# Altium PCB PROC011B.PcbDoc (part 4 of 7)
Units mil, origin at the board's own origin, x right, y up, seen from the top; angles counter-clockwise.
Board outline 3304 x 2569 mil, 6 copper layers (TOP, L2-GND1, L3-GND/SIG, L4-GND/SIG, L5-GND2, BOTTOM), stack 55.77 mil thick; 376 components, 289 nets, 1284 pads, 1755 vias.
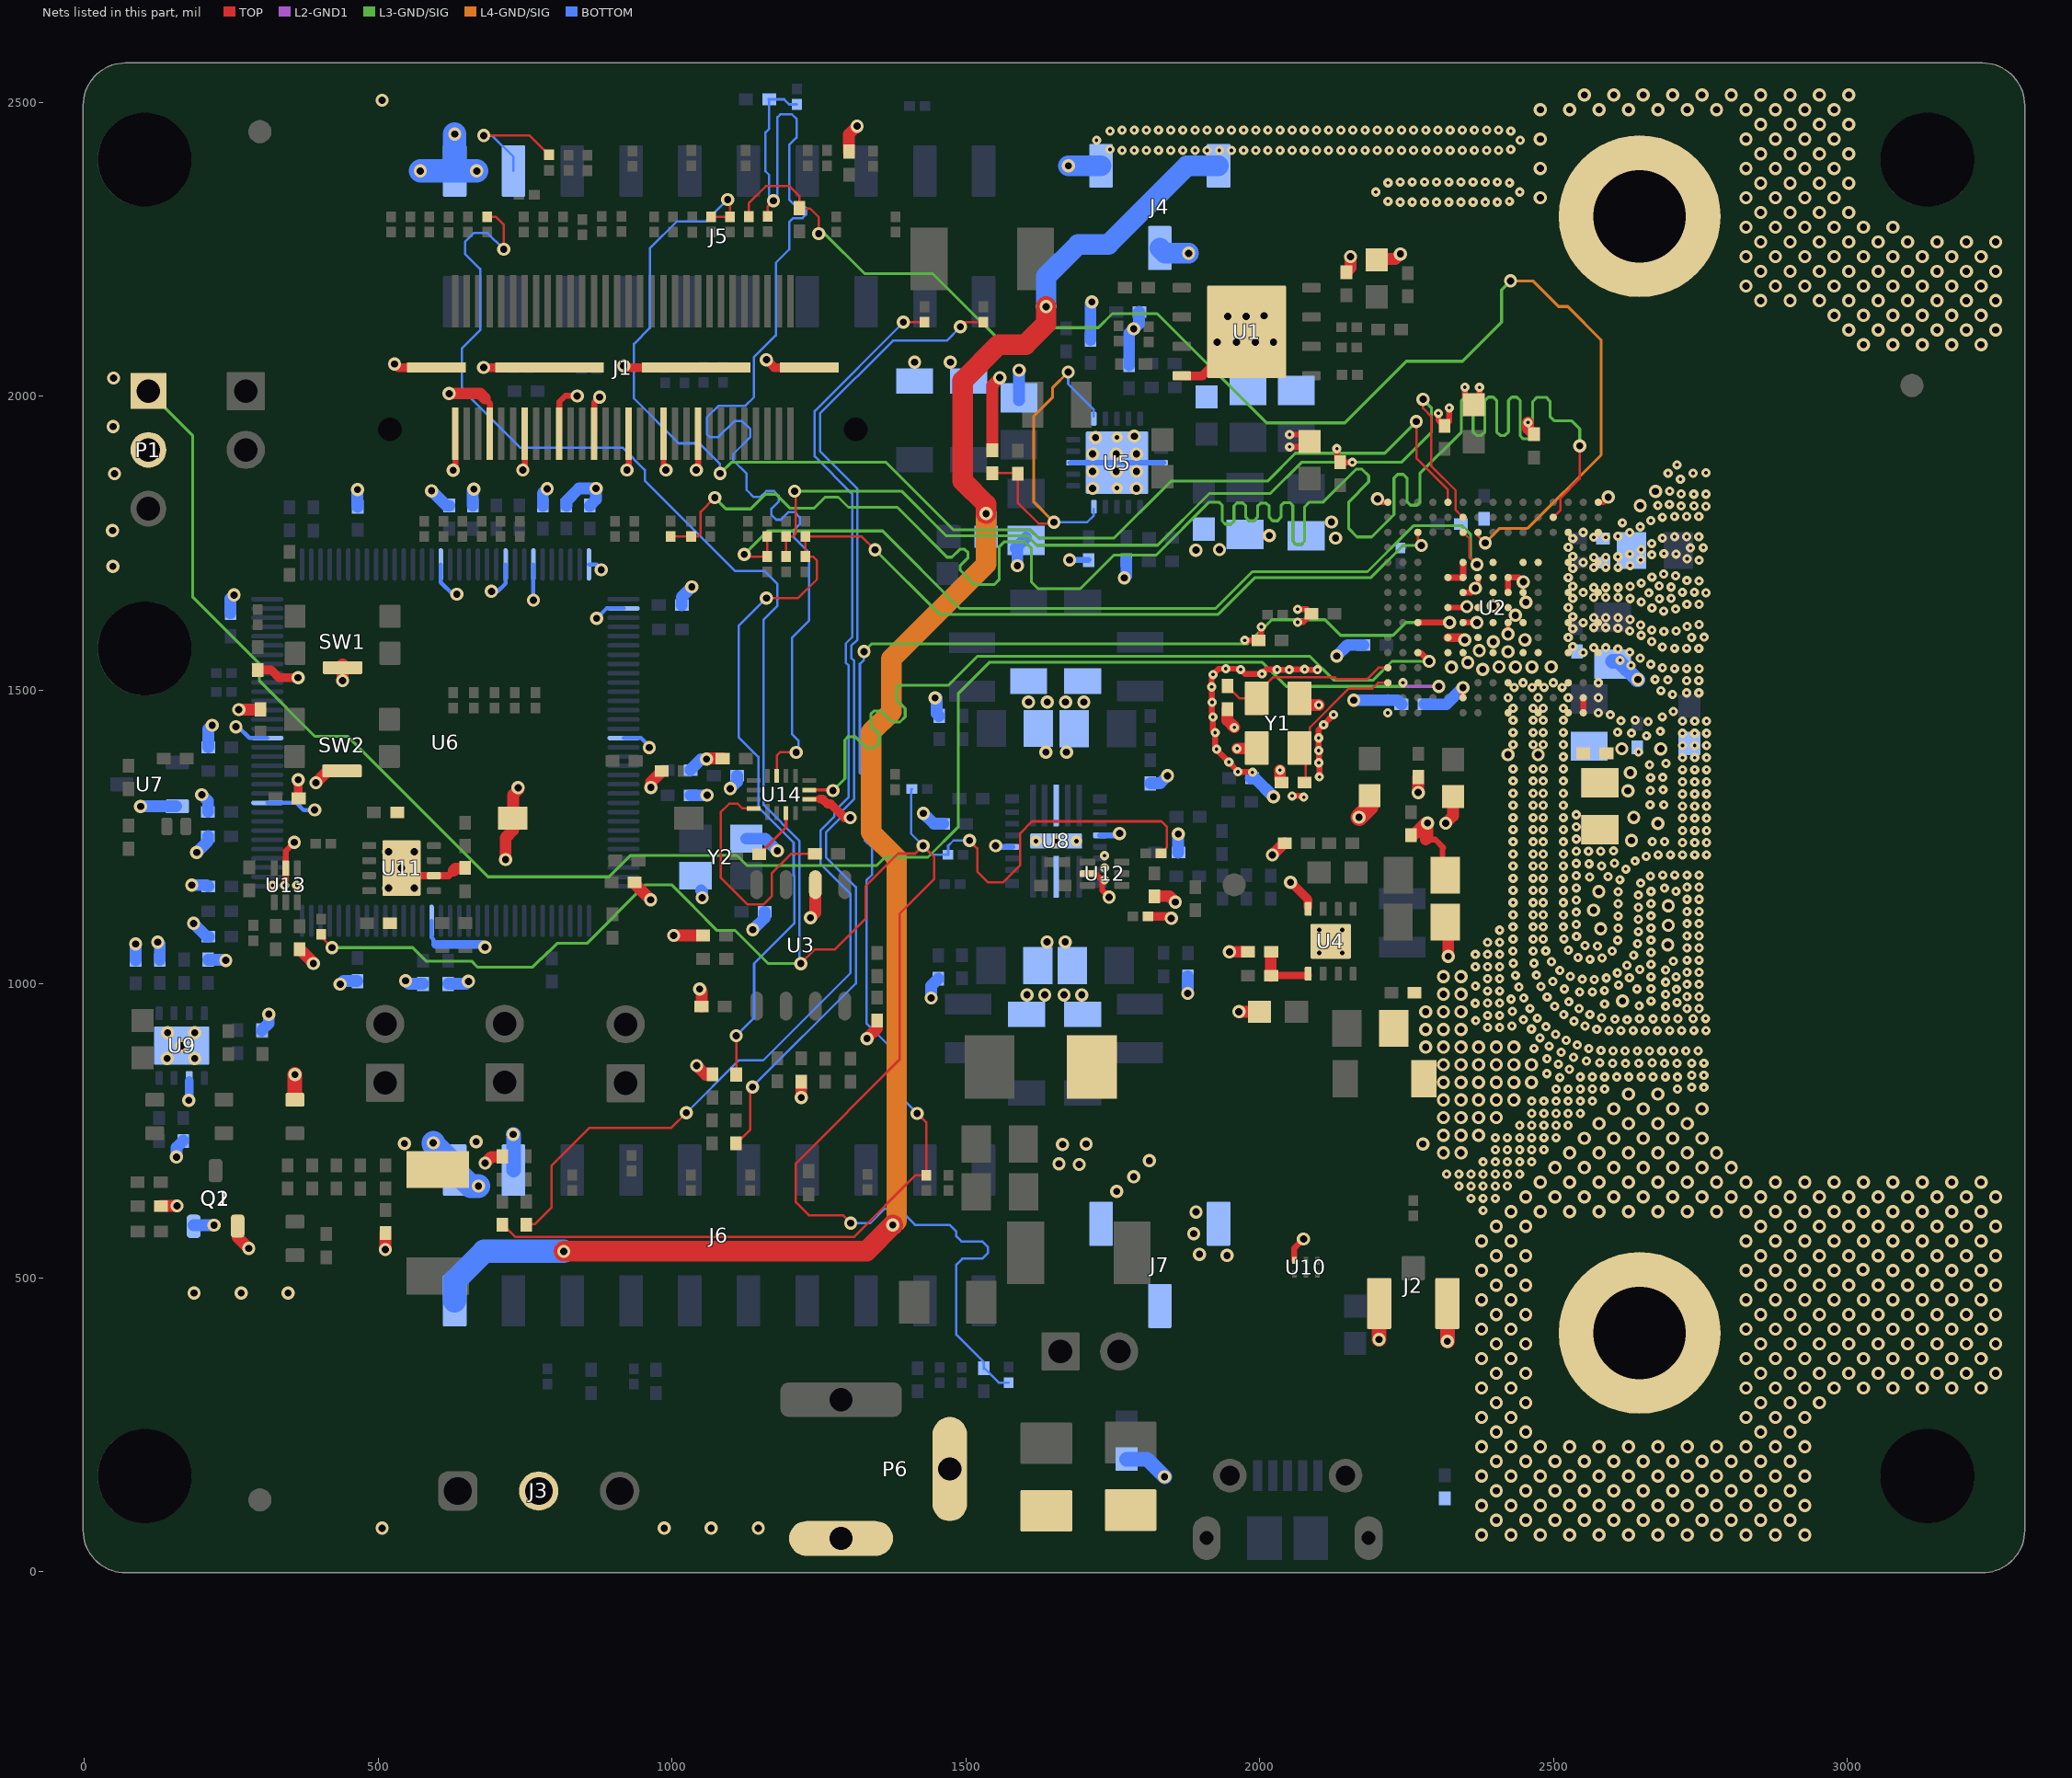
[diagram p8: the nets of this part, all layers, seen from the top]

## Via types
v1: diameter 22.4, hole 12.2, TOP to BOTTOM, tented both sides, 1046 vias
v2: diameter 13.77/15.74 (per signal layer), hole 5.9, TOP to L2-GND1, tented both sides, 699 vias
v3: diameter 19.68, hole 7.87, TOP to BOTTOM, tented both sides, 9 vias
v4: diameter 15.74, hole 5.9, TOP to L2-GND1, tented both sides, 1 vias

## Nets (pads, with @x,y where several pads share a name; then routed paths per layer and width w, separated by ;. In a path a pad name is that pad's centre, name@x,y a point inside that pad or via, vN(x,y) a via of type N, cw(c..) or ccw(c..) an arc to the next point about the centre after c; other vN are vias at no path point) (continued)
AR_SDA: R23.1 R144.2 R162.1 R168.2 R170.1 R199.2 R211.1 | length 5223.1
  TOP w4: R199.2@403.05,1084.31 403.05,1080.1 v1(421.55,1061.6) ; R23.1@685.36,2305.21 700.04,2305.21 713.75,2291.5 v1(713.75,2250) ; v1(1219.15,1034.5) 1243.45,1058.8 1277.45,1058.8 1329.5,1110.85 1329.5,1166.5 1384.75,1221.75 1413.95,1221.75 v1(1427.37,1235.17) 1446.25,1216.29 1446.25,1178.6 1387.15,1119.5 1387.15,870.9 1210.75,694.5 1210.75,628.61 1232.86,606.5 1290.75,606.5 v1(1304.25,593) ; v1(1506.45,1244.07) 1506.45,1243.8 1519.65,1230.6 1519.65,1191.2 1538.35,1172.5 1563.04,1172.5 1592.55,1202.01 1592.55,1256.3 1612.75,1276.5 1833.14,1276.5 1842.05,1267.59 1842.05,1232.11 R168.2@1832.34,1222.4
  L3-GND/SIG w5: v1(421.55,1061.6) 558.75,1061.6 581.55,1038.8 659.05,1038.8 669.55,1028.3 762.45,1028.3 776.95,1042.8 778.15,1042.8 804.35,1069 855.35,1069 955.01,1168.66 999.45,1168.66 1037.45,1130.66 1037.45,1130.19 1076.79,1090.85 1107.71,1090.85 1164.06,1034.5 v1(1219.15,1034.5)
  BOTTOM w4: v1(713.75,2250) 686.25,2277.5 662.75,2277.5 647.75,2262.5 647.75,2242.5 673.75,2216.5 673.75,2112.5 642.75,2081.5 642.75,2011.5 741.75,1912.5 915.75,1912.5 953.75,1874.5 953.75,1863.8 953.65,1863.7 953.65,1856.3 1107.45,1702.5 1157.75,1702.5 1179.65,1680.6 1179.65,1643.6 1155.92,1619.87 1155.92,1304.36 1217.15,1243.13 1217.15,1036.5 v1(1219.15,1034.5) ; v1(1304.25,593) 1337.45,593 1361.95,617.5 1386.15,617.5 1413.65,590 1472.2,590 1483.75,578.45 1483.75,570.43 1492.38,561.8 1528.27,561.8 1537.97,552.1 1537.97,542.78 1527.72,532.53 1494.11,532.53 1483.75,522.17 1483.75,403 1530.77,355.98 R170.1@1530.77,346.04 1530.77,345.25 1532.49,345.25 1555.95,321.79 R162.1@1573,321.79 ; R211.1@1408.17,1331.73 1407.05,1330.61 1407.05,1255.49 v1(1427.37,1235.17) 1442.94,1219.6 R144.2@1469.76,1219.6 1470.06,1219.6 1470.06,1235.11 1479.02,1244.07 v1(1506.45,1244.07)
AR_SPICLK1: U2.E13 U14.7 | length 1373.8
  TOP w5: U14.7@1233.51,1330.08 1272.86,1330.08 v1(1274.01,1328.93)
  TOP w10: U2.E13@2269.35,1563.63 2273.63,1563.63 v1(2288.46,1548.8)
  L3-GND/SIG w5: v1(1274.01,1328.93) 1294.43,1349.35 1294.43,1415.08 1299.93,1420.59 1311.84,1420.59 1330.71,1401.72 1344.05,1401.72 1353.12,1410.79 1353.12,1423.66 1353.6,1424.14 1338.32,1439.42 1338.32,1458.98 1343.72,1464.37 1355.7,1464.37 1374.57,1445.5 1387.91,1445.5 1396.98,1454.57 1396.98,1468.4 1382.18,1483.2 1382.18,1502.76 1387.55,1508.13 1387.55,1508.2 1470.56,1508.2 1519.86,1557.5 2085.36,1557.5 2125.86,1517 2193.35,1517 2225.15,1548.8 v1(2288.46,1548.8)
AR_SYNC_IN: R62.2 R165.1 U2.P4 | length 3219.4
  TOP w4: R165.1@997.75,1761.51 1032.32,1761.51 R62.2@1032.6,1761.23 1044.08,1761.23 1048.75,1765.9 1048.75,1803.5 v1(1072.75,1827.5) ; U2.P4@2499.66,1793.94 2512.25,1806.53 2512.25,1826.82 2544.75,1859.32 v1(2544.75,1915.5)
  L3-GND/SIG w5: v1(1072.75,1827.5) 1091.85,1808.4 1133.95,1808.4 1158.95,1833.4 1176.85,1833.4 1201.05,1809.2 1241.45,1809.2 1260.45,1828.2 1282.95,1828.2 1300.15,1811 1383.25,1811 1468.04,1726.21 1476.32,1726.21 1489.69,1739.58 1497.97,1739.58 1503.84,1733.71 1503.84,1725.43 1490.47,1712.06 1490.47,1703.78 1514.75,1679.5 1548.75,1679.5 1556.75,1687.5 1556.75,1743.5 1565.75,1752.5 1599.75,1752.5 1611.75,1740.5 1611.75,1683.5 1622.75,1672.5 1694.75,1672.5 1751.75,1729.5 1823.65,1729.5 1913.55,1819.4 1931.45,1819.4 1936.45,1814.4 1936.45,1787.45 1941.45,1782.45 1951.41,1782.45 1956.45,1787.49 1956.45,1813.3 1961.45,1818.3 1971.45,1818.3 1976.45,1813.3 1976.45,1793.91 1982.31,1788.05 1990.59,1788.05 1996.45,1793.91 1996.45,1812.9 2001.45,1817.9 2011.45,1817.9 2016.45,1812.9 2016.45,1793.91 2022.31,1788.05 2030.59,1788.05 2036.45,1793.91 2036.45,1813.9 2041.45,1818.9 2051.45,1818.9 2056.45,1813.9 2056.45,1753.05 2061.45,1748.05 2071.45,1748.05 2076.45,1753.05 2076.45,1811.4 2084.85,1819.8 2108.05,1819.8 2164.05,1875.8 2174.35,1875.8 2185.76,1864.39 2185.76,1854.21 2151.75,1820.2 2151.75,1774.5 2165.75,1760.5 2190.75,1760.5 2228.75,1798.5 2228.75,1860.9 2234.75,1866.9 2244.75,1866.9 2250.75,1860.9 2250.75,1820.49 2256.74,1814.5 2267.75,1814.5 2272.75,1819.5 2272.75,1868.5 2343.41,1939.16 2343.41,1992.64 2349.27,1998.5 2357.55,1998.5 2363.41,1992.64 2363.41,1939.16 2369.27,1933.3 2377.55,1933.3 2383.41,1939.16 2383.41,1992.64 2389.27,1998.5 2397.55,1998.5 2403.41,1992.64 2403.41,1939.16 2409.27,1933.3 2417.55,1933.3 2423.41,1939.16 2423.41,1992.64 2429.27,1998.5 2437.55,1998.5 2443.41,1992.64 2443.41,1932.54 2448.45,1927.5 2459.65,1927.5 2464.65,1932.5 2464.65,1990.7 2472.05,1998.1 2487.65,1998.1 2494.25,1991.5 2494.25,1965.3 2501.25,1958.3 2530.55,1958.3 2544.75,1944.1 v1(2544.75,1915.5)
AR_SYNC_OUT_SOP1: R108.2 R113.1 U2.G13 | length 2815.8
  TOP w4: R113.1@711.67,591.15 712.06,590.76 733.52,569.3 1309.54,569.3 1414.81,674.57 R108.2@1433.1,674.57 1433.1,763.85 v1(1417.3,779.65)
  TOP w10: U2.G13@2269.35,1614.81 2305.01,1614.81 2305.1,1614.9 v1(2323.3,1614.9)
  L3-GND/SIG w5: v1(1326.75,1565.5) 1340.05,1578.8 1980.05,1578.8 2020.85,1619.6 2111.35,1619.6 2137.85,1593.1 2226.95,1593.1 2248.75,1614.9 v1(2323.3,1614.9)
  BOTTOM w4: v1(1326.75,1565.5) 1326.75,1551.2 1319.75,1544.2 1319.75,1359.13 1327.71,1351.17 1327.71,1244.52 1340.53,1231.7 1340.53,1185.67 1330.95,1176.09 1330.95,933.2 1367.55,896.6 1367.55,829.4 v1(1417.3,779.65)
AR_TCK: R66.2 R70.1 U2.P10 | length 1617.8
  TOP w4: R70.1@1194.08,1727.21 1194.5,1727.63 R66.2@1194.5,1761.23 1205.48,1761.23 1210.75,1766.5 1210.75,1836.5 v1(1208.75,1838.5) ; v1(2278.15,1994.7) 2278.15,1979.6 2292.35,1965.4 2292.35,1880.9 2333.55,1839.7 2333.55,1806.54 2336.44,1803.65 2336.44,1803.55 2346.05,1793.94 U2.P10@2346.12,1793.94
  L3-GND/SIG w5: v1(1208.75,1838.5) 1390.35,1838.5 1466.35,1762.5 1604.75,1762.5 1620.75,1746.5 1826.45,1746.5 1914.45,1834.5 2018.15,1834.5 2071.15,1887.5 2241.45,1887.5 2292.35,1938.4 2292.35,1980.5 v1(2278.15,1994.7)
AR_TDI: R29.1 R30.1 U2.R11 | length 2192.5
  TOP w4: R29.1@1066.58,2305.21 R30.1@1098.5,2305.21 1098.5,2330.75 v1(1094.75,2334.5) ; v1(2266.75,1956.9) 2266.75,1894.5 2320.53,1840.72 U2.R11@2320.53,1819.53
  L3-GND/SIG w5: v1(1081.75,1868.5) 1100.75,1887.5 1364.35,1887.5 1479.35,1772.5 1609.75,1772.5 1623.75,1758.5 1752.05,1758.5 1849.05,1855.5 2013.35,1855.5 2060.85,1903 2212.85,1903 v1(2266.75,1956.9)
  BOTTOM w4: v1(1081.75,1868.5) 1081.75,1884.5 1046.48,1919.77 1011.72,1919.77 935.45,1996.04 935.45,2089.06 962.51,2116.12 962.51,2251.26 1008.75,2297.5 1057.75,2297.5 v1(1094.75,2334.5)
AR_TDO_SOP0: R67.2 R71.1 R89.1 U2.N13 | length 2275.2
  TOP w4: v1(1109.25,911.8) 1109.33,911.72 R89.1@1109.33,845.74 R89.1@1109.33,844.95 ; v1(1160.75,1656.5) 1214.75,1656.5 1246.75,1688.5 1246.75,1720.5 1240.04,1727.21 R71.1@1227.08,1727.21 1227,1727.29 R67.2@1227,1761.23 1323.02,1761.23 v1(1345.65,1738.6) ; U2.N13@2269.35,1768.35 2269.35,1752 v1(2275.25,1746.1)
  L3-GND/SIG w5: v1(1345.65,1738.6) 1455.45,1628.8 1929.45,1628.8 1992.15,1691.5 2189.55,1691.5 2244.15,1746.1 v1(2275.25,1746.1)
  BOTTOM w4: v1(1109.25,911.8) 1139.75,942.3 1139.75,1034.5 1208.15,1102.9 1208.15,1183.39 1207.05,1184.49 1207.05,1240.5 1146.92,1300.63 1146.92,1386.08 1113.84,1419.16 1113.84,1609.59 v1(1160.75,1656.5)
AR_TMS: R65.2 R69.1 U2.N10 | length 1566.1
  TOP w4: v1(1123.11,1730.85) 1126.75,1727.21 R69.1@1162,1727.21 R65.2@1162,1761.23 ; U2.N10@2346.12,1768.35 2357.07,1757.4 2357.07,1726.57 v1(2369.94,1713.7)
  L3-GND/SIG w5: v1(1123.11,1730.85) 1162.86,1770.6 1358.45,1770.6 1490.25,1638.8 1925.25,1638.8 1987.95,1701.5 2183.75,1701.5 2261.75,1779.5 2344.75,1779.5 2358.75,1765.5 2358.75,1724.89 v1(2369.94,1713.7)
AR_VBGAP: C56.2 U2.B10 | length 95.2
  TOP w10: U2.B10@2346.12,1486.86 v1(2346.12,1504.3)
  BOTTOM w20: C56.2@2280.2,1475.8 C56.2@2280.59,1475.8 2317.62,1475.8 v1(2346.12,1504.3)
AR_VOUT_PA: C10.2 C65.2 C83.2 R137.2 U2.A2 U2.B2 | length 44.9
  TOP w10: U2.A2@2550.84,1461.27 U2.B2@2550.84,1486.86 ; C83.2@2579.15,1342.15 C83.2@2592.8,1328.5
  other v1: 2626.75,1328.5 2630.75,1359.5
AR_VSENSE: P1.1 U2.C14 | length 3095.5
  L2-GND1 w5: v2(2243.76,1512.45) 2249.91,1506.3 v1(2304.85,1506.3)
  L3-GND/SIG w5: P1.1@109.02,2008.65 184.25,1933.42 184.25,1658.5 297.95,1544.8 297.95,1515.3 391.75,1421.5 447.65,1421.5 686.85,1182.3 893.05,1182.3 929.45,1218.7 1079.78,1218.7 1079.92,1218.56 1110.25,1218.56 1127.41,1201.4 1348.65,1201.4 1362.72,1215.47 1435.53,1215.47 1487.45,1267.39 1487.45,1494.47 1540.13,1547.15 2004.69,1547.15 2045.54,1506.3 v1(2304.85,1506.3)
AR_WARMRST: R15.1 R18.1 U2.N9 | length 2374.3
  TOP w4: R18.1@1130.96,2305.56 1130.96,2328.72 1159.74,2357.5 1199.74,2357.5 1216.75,2340.49 R15.1@1216.75,2320.04 1216.75,2319.25 1234.99,2319.25 1249.75,2304.49 v1(1249.75,2276.5) ; U2.N9@2371.71,1768.35 2371.71,1762.58 v1(2383.94,1750.35)
  L3-GND/SIG w5: v1(1249.75,2276.5) 1259.75,2276.5 1327.75,2208.5 1443.74,2208.5 1511.74,2140.5 1561.75,2090.5 1624.55,2090.5 1650.75,2116.7 1725.55,2116.7 1749.35,2140.5 1825.65,2140.5 2011.65,1954.5 2144.85,1954.5 2249.85,2059.5 2345.25,2059.5 2411.75,2126 2411.75,2181 v1(2426.95,2196.2)
  L4-GND/SIG w5: v1(2383.94,1750.35) 2408.69,1775.1 2456.15,1775.1 2581.15,1900.1 2581.15,2095.7 2524.35,2152.5 2508.95,2152.5 2465.25,2196.2 v1(2426.95,2196.2)
AR_XTALM: C9.2 U2.D15 Y1.1 | length 310.5
  TOP w4: C9.2@1945.11,1506.53 1965.68,1485.96 Y1.1@1995.05,1485.96 1995.05,1494.1 2022.55,1521.6 2128.25,1521.6 2131.35,1518.5 2182.76,1518.5 2202.3,1538.04 U2.D15@2218.17,1538.04
AR_XTALP: C15.2 U2.C15 Y1.3 | length 269.3
  TOP w4: C15.2@2078.45,1342.9 2078.28,1343.07 2078.28,1390.93 Y1.3@2067.89,1401.32 2085.45,1418.88 2085.45,1436.2 2151.75,1502.5 2191.75,1502.5 2201.7,1512.45 U2.C15@2218.17,1512.45
CAN_RX: R12.1 U14.3 | length 88.9
  TOP w5: R12.1@1148.6,1220.7 1148.6,1220.88 1194.14,1266.43 U14.3@1194.14,1290.71
CAN_TX: R11.1 U14.16 | length 414.6
  TOP w4: U14.16@1139.03,1298.59 1119.85,1298.59 1111.77,1306.66 1097.53,1306.66 1082.75,1291.88 1082.75,1181.16 1128.82,1135.09 1155.63,1135.09 1170.22,1149.68 1170.22,1188.61 1203.03,1221.42 R11.1@1243.26,1221.42
CS1: R1.2 R14.1 R17.1 U14.11 | length 2014.1
  TOP w4: R17.1@1163,2306.21 1163,2322.75 v1(1172.75,2332.5) ; U14.11@1178.4,1353.71 1178.4,1388.61 1183.82,1394.03 v1(1211.3,1394.03)
  BOTTOM w4: R14.1@1164.55,2505.1 1164.94,2504.71 R14.1@1165.33,2504.32 ; v1(1211.3,1394.03) 1215.55,1398.28 1215.55,1413.8 1204.58,1424.77 1204.58,1589.33 1233.65,1618.4 1233.65,1733.6 1207.37,1759.88 1207.37,1771.75 1217.45,1781.83 1217.45,1793.84 1208.44,1802.85 1198.4,1802.85 1185.43,1789.88 1177.37,1789.88 1169.46,1797.79 1169.46,1808.62 1181.52,1820.68 1181.52,1830.71 1173.46,1838.77 1160.66,1838.77 1150.25,1828.36 1138.89,1828.36 1126.93,1840.32 1126.93,1867.97 1104.17,1890.73 1104.17,1901.36 1133.26,1930.45 1133.26,1943.7 1118.91,1958.05 1106.58,1958.05 1079.08,1930.56 1064.35,1930.56 1059.53,1935.37 1059.53,1964.01 1079.32,1983.8 1125.15,1983.8 1139.72,1998.38 1139.72,2066.57 1176.75,2103.6 1176.75,2226.9 1199.45,2249.6 1199.45,2295.83 1206.59,2302.97 1222.11,2302.97 1228.57,2309.43 1228.57,2319.78 1221.17,2327.18 1206.59,2327.18 1199.45,2334.32 1199.45,2427.51 1212.05,2440.11 1212.05,2471.94 1204.37,2479.62 1184.3,2479.62 1179.41,2474.73 1179.41,2339.16 v1(1172.75,2332.5) 1165.33,2339.92 1165.33,2376.39 1159.09,2382.63 1159.09,2448.81 1165.33,2455.05 R14.1@1165.33,2504.32 ; R14.1@1165.33,2504.32 R14.1@1165.33,2505.1 1190.75,2505.1 1199.34,2496.51 ; 1199.34,2496.51 R1.2@1212.55,2496.51 1199.34,2496.51
D_LOGGER: J5.4 R60.1 | length 214.1
  TOP w4: v1(679.75,2443.5) 757.74,2443.5 R60.1@790.75,2410.49
  BOTTOM w4: v1(679.75,2443.5) 693.75,2443.5 730.25,2407 J5.4@730.25,2383.22
GND: C1.1 C2.1 C3.1 C4.1 C5.1 C6.1 C7.1 C8.1 C9.1 C10.1 C11.1 C12.1 C13.1 C14.1 C15.1 C16.1 C17.1 C19.1 C20.1 C21.1 C22.1 C23.1 C24.1 C25.1 C26.2 C27.2 C29.1 C30.1 C31.1 C32.1 C33.1 C34.1 C35.1 C36.1 C37.1 C38.1 C39.1 C40.1 C41.1 C42.1 C43.1 C44.1 C45.1 C47.1 C48.1 C49.1 C50.1 C51.1 C52.1 C53.1 C54.1 C55.1 C56.1 C57.1 C58.1 C59.1 C60.1 C61.1 C62.1 C63.1 C64.1 C65.1 C66.1 C67.1 C68.1 C69.1 C70.1 C71.1 C72.1 C73.1 C74.1 C75.1 C76.1 C77.1 C79.1 C80.1 C81.1 C82.1 C83.1 C84.1 C85.1 C86.1 C87.1 C89.1 C90.1 C91.1 C92.1 C93.1 C94.1 C95.1 C96.1 C97.1 D3.2 DS2.2 J1.18 J1.24 J1.30 J1.36 J1.42 J1.48 J1.54 J1.60 J1.MP1 J1.MP2 J1.MP3 J1.MP4 J2.2 J2.3 J3.2 J4.1 J4.2 J5.2 J6.4 J7.1 J7.2 P1.2 P6.2 P6.3 pad.1 pad.2 Q1.2 Q2.2 R13.1 R47.2 R73.1 R79.1 R81.1 R83.2 R86.2 R88.1 R96.1 R110.1 R114.1 R119.1 R121.1 R123.2 R125.1 R126.2 R132.1 R138.1 R139.1 R153.1 R157.1 R158.1 R167.1 R174.1 R175.1 R193.1 R208.2 S2.1 SW1.5 SW2.5 U1.4 U1.9 U2.A1 U2.A3 U2.A5 U2.A7 U2.A15 U2.B1 U2.B3 U2.B5 U2.B7 U2.C1 U2.C3 U2.C4 U2.C5 U2.C6 U2.C7 U2.E1 U2.E2 U2.E3 U2.E5 U2.E6 U2.E8 U2.E10 U2.E11 U2.F3 U2.F9 U2.F11 U2.G1 U2.G2 U2.G3 U2.G6 U2.G7 U2.G8 U2.G10 U2.H3 U2.H7 U2.H9 U2.H11 U2.J1 U2.J2 U2.J3 U2.J6 U2.J7 U2.J8 U2.J10 U2.K3 U2.K7 U2.K8 U2.K9 U2.K10 U2.K11 U2.L1 U2.L2 U2.L3 U2.L5 U2.L6 U2.L8 U2.L10 U2.M3 U2.N1 U2.N2 U2.N3 U2.R1 U2.R15 U3.2 U4.4 U4.9 U5.3 U5.13 U5.21@1757.37,1886.82 U6.10 U6.17 U6.48 U6.55 U6.58 U6.64 U6.66 U6.80 U6.114 U7.2 U8.4 U8.11 U8.17 U8.24 U8.27 U9.6 U9.9 U10.3 U11.6 U11.9 U12.2 U13.2 U14.6 Y1.2 Y1.4 Y2.2 Y2.4 | length 8140.2
  TOP w7: U14.6@1233.51,1314.34 1252.42,1314.34 ; U2.J7@2421.64,1665.99 U2.J7@2422.89,1665.99 U2.J7@2423.36,1665.99 ; U2.G7@2422.89,1614.81 U2.G7@2422.89,1614.81 v1@2422.89,1595.21
  TOP w9: v1(2367.2,1673.3) 2371.71,1677.81 U2.K9@2371.71,1691.58
  TOP w10: v2@342.75,1175.5 342.75,1226.3 v1(357.35,1240.9) ; v1(627.73,1874.03) 631.37,1877.67 J1.60@631.37,1935.77 ; 681.75,1996.5 690.42,1987.83 J1.54@690.42,1935.77 ; v1(746.28,1874.47) 749.48,1877.67 J1.48@749.48,1935.77 ; J1.42@808.53,1935.77 808.53,1990.5 818.53,2000.5 v1(838.75,2000.5) ; J1.36@867.59,1935.77 867.59,1989.34 v1(876.75,1998.5) ; v1(923.36,1874.39) 926.64,1877.67 J1.30@926.64,1935.77 ; J1.24@985.7,1935.77 985.7,1878.55 v1(989.75,1874.5) ; v1(1041.42,1874.34) 1044.75,1877.67 J1.18@1044.75,1935.77 ; U12.2@1707.12,1187.4 1720.95,1187.4 1732.15,1176.2 1732.15,1159.4 v1(1743.95,1147.6) ; v2(1974.75,1584.5) C84.1@1998.07,1584.5 1998.45,1584.5 2002.75,1588.8 v2(2002.75,1607.5) ; v2(1987.75,1360) 1987.75,1360.9 v2(1962.85,1360.9) 1962.85,1362.4 v2(1947.75,1377.5) 1926.75,1398.5 v2(1926.75,1399.5) 1924.35,1401.9 v2(1924.35,1427.5) 1920.45,1431.4 v2(1920.45,1454) 1919.05,1455.4 v2(1919.05,1479.1) 1919.05,1504.8 v2(1918.45,1505.4) 1918.45,1524.2 v2(1920.75,1526.5) 1930.65,1536.4 v2(1942.45,1536.4) 1966.35,1536.4 v2(1967.75,1535) 1975.35,1527.4 v2(2004.05,1527.4) 2011.55,1534.9 v2(2029.75,1534.9) 2030.15,1534.5 v2(2050.35,1534.5) 2051.18,1535.33 v2(2076.77,1535.33) 2077.7,1534.4 2098.45,1534.4 v2(2098.55,1534.5) ; v2(2051.05,1913.8) 2075.75,1913.8 C89.1@2084.85,1922.9 2073.15,1934.6 v2(2051.05,1934.6) ; v2(2055.37,1319.8) 2073.05,1319.8 v2(2075.15,1317.7) ; U10.3@2059.07,529.81 2059.06,550.31 v1(2074.75,566) ; v2(2064.75,1615.5) 2074.07,1615.5 2088.42,1629.85 2080.77,1637.5 v2(2064.75,1637.5) ; v2(2101.85,1352.2) 2101.85,1375.3 v2(2100.85,1376.3) 2100.85,1396.5 v2(2100.45,1396.9) v2(2100.45,1418.6) 2100.45,1432.5 v2(2108.95,1441) v2(2125.9,1457.95) ; v2(2131.55,1910.8) 2131.55,1893.1 2137.25,1887.4 v2(2158.05,1887.4) ; v1(2200.75,1825.3) 2206.52,1819.53 U2.R15@2218.17,1819.53 ; C90.1@2261.63,1253.2 2275.05,1253.2 2282.75,1245.5 2298.85,1245.5 2312.55,1231.8 2311.25,1230.5 C17.1@2311.25,1185.1 ; v2(2304.15,1970.9) 2304.15,1959.4 2314.15,1949.4 2314.7,1949.4 2322.65,1957.35 v2(2322.65,1980.3) ; U2.H11@2320.53,1640.4 2351.3,1640.4 v1(2352.8,1641.9) ; U2.G10@2346.12,1614.81 v1@2369.69,1614.81 ; U2.J10@2346.12,1665.99 2359.89,1665.99 v1(2367.2,1673.3) ; v2(2349.35,2015.2) 2349.35,2000.05 2364,1985.4 C87.1@2364.55,1985.4 2374.25,1995.1 v2(2374.25,2015) ; U2.J7@2422.89,1665.99 U2.K7@2422.89,1691.58 2441.17,1691.58 v1(2448.75,1684) ; U2.R1@2576.43,1819.53 2584.43,1819.53 v1(2593.3,1828.4)
  TOP w11: U2.K11@2320.53,1691.58 U2.K10@2346.12,1691.58 U2.L10@2346.12,1717.17
  TOP w12: v1(539.65,1197) 552.45,1184.2 619.65,1184.2 628.45,1193
  TOP w15: R73.1@294.8,1534.52 317.73,1534.52 331.25,1521 v1(363.75,1521) ; R79.1@363.9,1315.64 v1(363.9,1347.5) ; v1(527.95,2054.8) 533.99,2048.76 J1.MP4@598.87,2048.76 J1.MP4@599.48,2048.76 ; v1(679.51,2048.76) J1.MP3@791.39,2048.76 J1.MP3@792,2048.76 ; v1(917.75,2051.5) 920.49,2048.76 J1.MP2@1041.39,2048.76 J1.MP2@1042,2048.76 ; v1(1160.75,2062) 1173.99,2048.76 J1.MP1@1233.91,2048.76 J1.MP1@1234.52,2048.76 ; 1252.42,1314.34 1256.5,1314.34 1264.61,1306.23 1270.12,1306.23 1293.63,1282.72 v1(1303.33,1282.72) ; R167.1@1810.34,1115.1 1846.25,1115.1 v1(1849.75,1111.6) ; U1.4@1865.68,2034.68 U1.4@1867.64,2034.68 1902.88,2034.68 U1.9@1977.88,2109.68 ; v1(2052.75,1173) 2082.54,1143.21 U4.4@2082.54,1130.54 ; U2.F11@2320.53,1589.22 2345.08,1589.22 v1(2349.1,1585.2)
  TOP w20: R110.1@129.37,622.27 R110.1@130.15,622.27 v1(157.75,622.27) ; Q1.2@260.73,589.97 260.73,569.02 v1(279.75,550) ; v1(262.75,1466.7) C11.1@300.05,1466.7 ; C92.1@366.35,1059.4 389.85,1035.9 v1(389.85,1034.8) ; v1(393.95,1342.2) 414.15,1362.4 SW2.5@438.45,1362.4 ; v1(439.4,1516) SW1.5@439.4,1538.02 SW1.5@439.4,1543.92 ; v1(512.27,548) R114.1@512.27,575.96 R114.1@512.27,576.75 ; v1(620.75,2004.5) 673.75,2004.5 681.75,1996.5 ; 628.45,1193 631.86,1196.41 R193.1@647.65,1196.41 ; v1(681.95,695) 692.6,705.65 R96.1@711.53,705.65 ; v1(716.81,1211.5) 716.81,1248.73 729.68,1261.6 729.68,1322.06 738.15,1330.53 v1(738.15,1333.88) ; C71.1@936.05,1173 936.05,1170.7 v1(963.75,1143) ; v1(964.01,1334.23) 964.01,1342.99 982.54,1361.53 C97.1@982.54,1361.93 ; v1(1002.75,1082.5) C16.1@1052.67,1082.5 C16.1@1053.05,1082.5 ; v1(1041.95,861.1) 1057.8,845.25 R88.1@1068.87,845.25 ; v1(1047.05,991.4) 1050.64,987.81 C20.1@1050.64,961.35 ; v1(1058.77,1382.5) 1059.89,1383.62 R208.2@1086.13,1383.62 ; v1(1219.85,806.6) C24.1@1219.85,833.92 C24.1@1219.85,834.3 ; v1(1235.75,1112.5) 1244.06,1120.81 U3.2@1244.06,1168.83 U3.2@1244.06,1169.81 ; R13.1@1301.15,2415.45 R13.1@1301.15,2416.24 1301.15,2445.5 v1(1315.15,2459.5) ; v1(1331.75,907) 1349.05,924.3 R86.2@1349.05,937.51 R86.2@1349.05,938.3 ; R47.2@1545.15,1907.3 R47.2@1545.15,1908.09 1545.15,2018.8 v1(1557.85,2031.5) ; C91.1@1821.15,1149.3 1846.45,1149.3 v1(1856.55,1139.2) ; C9.1@1945.11,1467.93 C9.1@1945.11,1467.54 1945.11,1448.44 v2(1957.05,1436.5) ; v1(1948.75,1054.52) R83.2@1980.41,1054.52 R83.2@1981.2,1054.52 ; v2(1961.75,1400.5) 1994.23,1400.5 Y1.2@1995.05,1401.32 ; v1(1964.75,952.77) C22.1@1999.72,952.77 ; v1(2021.75,1219.5) 2041.92,1239.67 R81.1@2042.96,1239.67 R81.1@2043.74,1239.67 ; C15.1@2034.75,1348 v2(2034.75,1363.8) ; Y1.4@2067.89,1485.96 2079.35,1474.5 v2(2100.75,1474.5) ; C2.1@2147.65,2210.7 C2.1@2147.65,2211.08 2154.75,2218.18 v1(2154.75,2237.5) ; C1.1@2199.35,2233.6 2231.15,2233.6 v1(2239.55,2242) ; C90.1@2257.75,1252.82 2261.25,1252.82 2261.63,1253.2 2282.23,1273.8 v1(2285.85,1273.8) 2285.85,1248.6 2282.75,1245.5 ; v1(2269.95,1325.6) C12.1@2269.95,1352.01 C12.1@2269.95,1352.4 ; C19.1@2311.1,1105.17 2321.05,1095.22 v1(2321.05,1046.7) ; v1(2316.75,1273.4) 2329.25,1285.9 C13.1@2329.25,1318.9 ; v4(2456.95,1955.3) 2456.95,1944.75 2466.95,1934.75 C3.1@2466.95,1935.14
  TOP w25: DS2.2@358.35,805.87 v1(358.35,845.9) ; v1(2203.39,395) J2.2@2203.39,456.22 ; v1(2319.53,392) J2.3@2319.53,456.22
  TOP w30: v1(2169.35,1283.5) 2187.2,1301.35 C14.1@2187.2,1320.4
  BOTTOM w7: v1(257.75,1437.5) 261.75,1437.5 280.84,1418.41 U6.17@311.39,1418.41 ; U6.10@311.39,1308.18 360.75,1308.18 373.53,1295.4 391.15,1295.4 391.15,1296.1 v1(391.85,1296.1) ; U6.114@590.92,1107.39 590.92,1078.73 594.15,1075.5 594.25,1075.5 594.25,1071 597.95,1067.3 ; U6.48@606.67,1713.69 606.67,1683.09 626.76,1663 v1(633.75,1663) ; v1(692.75,1668) 703.75,1668 716.9,1681.15 U6.55@716.9,1713.69 ; v1(764.15,1652.8) U6.58@764.15,1713.69 ; U6.64@858.63,1713.69 871.75,1713.69 879.75,1705.69 v1(879.75,1704.5) ; v1(871.75,1622) 888.64,1638.89 U6.66@917.69,1638.89 ; U6.80@917.69,1418.41 947.24,1418.41 v1@963.61,1402.04 ; v1(961.45,1402.04) v1@963.61,1402.04 ; v1@967.75,1397.9 v1@963.61,1402.04
  BOTTOM w10: v1(1550.85,1235) 1551.3,1235 1551.3,1235.05 1553.19,1233.16 U8.4@1578.95,1233.16 ; v1(1676.75,1721.45) C44.1@1708.92,1721.45 ; U5.3@1682.57,1886.82 U5.3@1678.63,1886.82 ; U5.21@1715.95,1886.82 U5.3@1678.63,1886.82 ; U8.17@1728.55,1252.84 1758.59,1252.84 v1(1761.75,1256) ; U5.21@1755.95,1886.82 U5.3@1678.63,1886.82 ; U5.21@1757.37,1886.82 U5.3@1678.63,1886.82 ; U5.21@1790.45,1886.82 U5.3@1678.63,1886.82 ; U5.13@1836.11,1886.82 U5.3@1678.63,1886.82
  BOTTOM w15: v1(177.75,802) 178.38,802 U9.6@178.38,835.82 ; 597.95,1067.3 677.05,1067.3 v1(681.85,1062.5)
  BOTTOM w20: C80.1@87.35,1040.3 C80.1@87.35,1040.68 v1(87.35,1068) ; v1(95.75,1302) 100.75,1302 100.75,1302.19 U7.2@156.11,1302.19 ; v1(124.75,1071) 128.37,1067.38 C79.1@128.37,1041.04 C79.1@128.37,1040.65 ; v1(156.75,705.5) 156.75,721.77 R158.1@168.43,733.45 ; v1(182.75,1168) 207.75,1168 209.69,1166.06 C69.1@210.71,1166.06 C69.1@211.1,1166.06 ; v1(185.75,1103) 208.51,1080.24 R153.1@210.71,1080.24 R153.1@211.5,1080.24 ; Q2.2@185.97,589.39 v1(220.75,589.39) ; v1(191.15,1223.6) 210.7,1243.15 C67.1@210.7,1251.3 ; v1(199.75,1322) 210.64,1311.11 C66.1@210.64,1292.6 ; C77.1@210.57,1040.95 236.75,1040.95 236.75,1040 v1(240.75,1040) ; C61.1@211.1,1402.56 211.1,1433.65 v1(217.45,1440) ; C50.1@248.7,1630.5 C50.1@248.7,1630.89 248.7,1655.65 v1(254.75,1661.7) ; R157.1@301.95,920.25 R157.1@301.95,921.04 313.75,932.83 v1(313.75,948.5) ; v1(435.35,999.4) 441,1005.05 C76.1@464.67,1005.05 ; v1(464.75,1841) 464.48,1840.73 464.48,1812.44 C43.1@465.27,1811.65 ; v1(546.75,1005.5) 551.9,1000.35 C75.1@576.43,1000.35 ; v1(590.75,1839) 616.1,1813.65 C42.1@620.97,1813.65 ; C74.1@619.35,1000.35 649.6,1000.35 v1(653.65,1004.4) ; C41.1@661.05,1813.65 C41.1@661.05,1814.04 661.05,1840.3 v1(662.75,1842) ; R125.1@780.27,1813.25 R125.1@780.27,1814.04 780.27,1835.02 v1(787.75,1842.5) ; R126.2@820.43,1813.55 R126.2@820.43,1814.34 820.43,1821.68 841.75,1843 v1(870.75,1843) 870.75,1824.27 R123.2@860.03,1813.55 ; C49.1@1016.4,1644.4 1016.4,1658.15 v1(1033.75,1675.5) ; C62.1@1031.4,1364 1049.9,1382.5 v1(1058.77,1382.5) ; C64.1@1031.7,1320.8 C64.1@1032.08,1320.8 1058.75,1320.8 1058.75,1321 v1(1059.75,1321) ; 1049.4,1159 1051.36,1157.04 v1(1051.36,1146.57) ; v1(1099.01,1332.3) 1110.68,1343.97 C63.1@1110.68,1354.35 ; Y2.2@1126.7,1247.08 1158.57,1247.08 v1(1179.2,1226.45) ; v1(1137.41,1092.2) 1157.62,1112.42 C70.1@1157.62,1122.7 ; v1(1427.8,1290.35) 1445.75,1272.4 R138.1@1461.17,1272.4 R138.1@1461.95,1272.4 ; v1(1441,975.95) 1441,996.86 C95.1@1453.15,1009.01 C95.1@1453.15,1009.4 ; v1(1447.75,1486.5) 1450.45,1486.5 1450.45,1460.08 C93.1@1454.45,1456.08 C93.1@1454.45,1455.7 ; v1(1587.75,1711.5) 1587.75,1738.45 1584.75,1741.45 C40.1@1602.7,1759.4 ; C32.1@1590.7,1992.9 C32.1@1590.7,1997.5 v1(1590.7,2044.2) ; C29.1@1712.22,2095.85 C29.1@1712.22,2096.24 1712.22,2158.17 v1(1714.45,2160.4) ; v1(1769.75,1691) 1773.22,1694.47 R132.1@1773.22,1721.17 R132.1@1773.22,1721.95 ; R121.1@1778.02,2052.29 R121.1@1778.02,2053.07 1778.02,2106.62 v1(1785.9,2114.5) 1794.65,2123.25 R119.1@1794.65,2143.5 ; C94.1@1814.05,1341.5 1830.55,1341.5 v1(1843.25,1354.2) ; C68.1@1861.5,1223.5 1861.5,1255 v1(1861.75,1255) ; v1(1877.85,983.8) C96.1@1877.85,1012.92 C96.1@1877.85,1013.3 ; R139.1@1985,1350.04 R139.1@1987.43,1350.04 1992.11,1350.04 v1(2023.7,1318.45) ; v1(2131.25,1558) 2149.75,1576.5 C53.1@2176.42,1576.5 C53.1@2176.8,1576.5 ; v1(2160.35,1482.6) 2234.8,1482.6 C56.1@2241.6,1475.8
  BOTTOM w25: v1(729.75,744) 730.25,744 J6.4@730.25,683.22 ; R175.1@1773.75,191.5 1808.25,191.5 v1(1838.25,161.5) ; C52.1@2600.9,1548.5 2611.55,1548.5 2642.25,1517.8 v1(2643.85,1517.8)
  BOTTOM w35: v1(1674.77,2391.98) J4.1@1730.25,2391.98 ; J4.2@1830.25,2252.02 1839.17,2243.1 v1(1879.35,2243.1)
  BOTTOM w40: v1(571.75,2383.22) J5.2@630.25,2383.22 ; v1(630.25,2446) J5.2@630.25,2383.22 ; v1(667.75,2383.22) J5.2@630.25,2383.22
  other v1: 2377.75,62.5 2427.75,62.5 2477.75,62.5 2527.75,62.5 2577.75,62.5 2627.75,62.5 2677.75,62.5 2727.75,62.5 2777.75,62.5 2827.75,62.5 2877.75,62.5 2927.75,62.5 506.75,74 986.75,74 1066.75,74 1146.75,74 2402.75,87.5 2452.75,87.5 2502.75,87.5 2552.75,87.5 2602.75,87.5 2652.75,87.5 2702.75,87.5 2752.75,87.5 2802.75,87.5 2852.75,87.5 2902.75,87.5 2377.75,112.5 2427.75,112.5 2477.75,112.5 2527.75,112.5 2577.75,112.5 2627.75,112.5 2677.75,112.5 2727.75,112.5 2777.75,112.5 2827.75,112.5 2877.75,112.5 2927.75,112.5 2402.75,137.5 2452.75,137.5 2502.75,137.5 2552.75,137.5 2602.75,137.5 2652.75,137.5 2702.75,137.5 2752.75,137.5 2802.75,137.5 2852.75,137.5 2902.75,137.5 2377.75,162.5 2427.75,162.5 2477.75,162.5 2527.75,162.5 2577.75,162.5 2627.75,162.5 2677.75,162.5 2727.75,162.5 2777.75,162.5 2827.75,162.5 2877.75,162.5 2927.75,162.5 2402.75,187.5 2452.75,187.5 2502.75,187.5 2552.75,187.5 2602.75,187.5 2652.75,187.5 2702.75,187.5 2752.75,187.5 2802.75,187.5 2852.75,187.5 2902.75,187.5 2377.75,212.5 2427.75,212.5 2477.75,212.5 2527.75,212.5 2577.75,212.5 2627.75,212.5 2677.75,212.5 2727.75,212.5 2777.75,212.5 2827.75,212.5 2877.75,212.5 2927.75,212.5 2402.75,237.5 2452.75,237.5 2852.75,237.5 2902.75,237.5 2377.75,262.5 2427.75,262.5 2827.75,262.5 2877.75,262.5 2927.75,262.5 2402.75,287.5 2452.75,287.5 2852.75,287.5 2902.75,287.5 2952.75,287.5 2377.75,312.5 2427.75,312.5 2827.75,312.5 2877.75,312.5 2927.75,312.5 2977.75,312.5 3027.75,312.5 3077.75,312.5 3127.75,312.5 3177.75,312.5 3227.75,312.5 2402.75,337.5 2452.75,337.5 2852.75,337.5 2902.75,337.5 2952.75,337.5 3002.75,337.5 3052.75,337.5 3102.75,337.5 3152.75,337.5 3202.75,337.5 3252.75,337.5 2377.75,362.5 2427.75,362.5 2827.75,362.5 2877.75,362.5 2927.75,362.5 2977.75,362.5 3027.75,362.5 3077.75,362.5 3127.75,362.5 3177.75,362.5 3227.75,362.5 2402.75,387.5 2452.75,387.5 2852.75,387.5 2902.75,387.5 2952.75,387.5 3002.75,387.5 3052.75,387.5 3102.75,387.5 3152.75,387.5 3202.75,387.5 3252.75,387.5 2377.75,412.5 2427.75,412.5 2827.75,412.5 2877.75,412.5 2927.75,412.5 2977.75,412.5 3027.75,412.5 3077.75,412.5 3127.75,412.5 3177.75,412.5 3227.75,412.5 2402.75,437.5 2452.75,437.5 2852.75,437.5 2902.75,437.5 2952.75,437.5 3002.75,437.5 3052.75,437.5 3102.75,437.5 3152.75,437.5 3202.75,437.5 3252.75,437.5 2377.75,462.5 2427.75,462.5 2827.75,462.5 2877.75,462.5 2927.75,462.5 2977.75,462.5 3027.75,462.5 3077.75,462.5 3127.75,462.5 3177.75,462.5 3227.75,462.5 186.75,474 266.75,474 346.75,474 2402.75,487.5 2452.75,487.5 2852.75,487.5 2902.75,487.5 2952.75,487.5 3002.75,487.5 3052.75,487.5 3102.75,487.5 3152.75,487.5 3202.75,487.5 3252.75,487.5 2377.75,512.5 2427.75,512.5 2827.75,512.5 2877.75,512.5 2927.75,512.5 2977.75,512.5 3077.75,512.5 3127.75,512.5 3177.75,512.5 3227.75,512.5 3026.75,514 2402.75,537.5 2452.75,537.5 2852.75,537.5 2902.75,537.5 2952.75,537.5 3002.75,537.5 3052.75,537.5 3102.75,537.5 3152.75,537.5 3202.75,537.5 3252.75,537.5 2377.75,562.5 2427.75,562.5 2827.75,562.5 2877.75,562.5 2927.75,562.5 2977.75,562.5 3027.75,562.5 3077.75,562.5 3127.75,562.5 3177.75,562.5 3227.75,562.5 2402.75,587.5 2452.75,587.5 2852.75,587.5 2902.75,587.5 2952.75,587.5 3002.75,587.5 3052.75,587.5 3102.75,587.5 3152.75,587.5 3202.75,587.5 3252.75,587.5 2427.75,612.5 2477.75,612.5 2527.75,612.5 2577.75,612.5 2627.75,612.5 2677.75,612.5 2727.75,612.5 2777.75,612.5 2827.75,612.5 2877.75,612.5 2927.75,612.5 2977.75,612.5 3027.75,612.5 3077.75,612.5 3127.75,612.5 3177.75,612.5 3227.75,612.5 2452.75,637.5 2502.75,637.5 2552.75,637.5 2602.75,637.5 2652.75,637.5 2702.75,637.5 2752.75,637.5 2802.75,637.5 2852.75,637.5 2902.75,637.5 2952.75,637.5 3002.75,637.5 3052.75,637.5 3102.75,637.5 3152.75,637.5 3202.75,637.5 3252.75,637.5 1756.85,647 2477.75,662.5 2527.75,662.5 2577.75,662.5 2627.75,662.5 2677.75,662.5 2727.75,662.5 2777.75,662.5 2827.75,662.5 2877.75,662.5 2927.75,662.5 2977.75,662.5 3027.75,662.5 3077.75,662.5 3127.75,662.5 3177.75,662.5 3227.75,662.5 1785.65,671.8 2502.75,687.5 2552.75,687.5 2602.75,687.5 2652.75,687.5 2702.75,687.5 2752.75,687.5 2802.75,687.5 1693.05,692.7 1658.75,693.9 1812.35,699.2 2312.75,712.5 2342.75,712.5 2527.75,712.5 2577.75,712.5 2627.75,712.5 2677.75,712.5 2727.75,712.5 2777.75,712.5 1664.65,726.9 1704.75,727.6 2277.75,727.5 2552.75,737.5 2602.75,737.5 2652.75,737.5 2702.75,737.5 2752.75,737.5 2312.75,742.5 2342.75,742.5 2372.75,742.5 2577.75,762.5 2627.75,762.5 2677.75,762.5 2727.75,762.5 2312.75,772.5 2342.75,772.5 2372.75,772.5 2402.75,772.5 2602.75,787.5 2652.75,787.5 2702.75,787.5 2752.75,787.5 2312.75,802.5 2342.75,802.5 2372.75,802.5 2402.75,802.5 2432.75,802.5 2627.75,812.5 2677.75,812.5 2312.75,832.5 2342.75,832.5 2372.75,832.5 2402.75,832.5 2432.75,832.5 2462.75,832.5 2312.75,862.5 2342.75,862.5 2372.75,862.5 2402.75,862.5 2432.75,862.5 2462.75,862.5 140.75,873 187.75,873 2282.75,892.5 2312.75,892.5 2342.75,892.5 2372.75,892.5 2402.75,892.5 2432.75,892.5 165.58,894.88 141.75,917 187.75,917 2282.75,922.5 2312.75,922.5 2342.75,922.5 2282.75,952.5 2312.75,952.5 2342.75,952.5 2617.65,970.8 1604.3,981.3 1634.3,981.3 1667.3,981.3 1697.3,981.3 2312.75,982.5 2342.75,982.5 2312.75,1012.5 2342.75,1012.5 2694.55,1066.4 1638.3,1071.3 1669.3,1071.3 2580.45,1093.9 2695.45,1099.6 2568.45,1125.4 2695.45,1133 2577.15,1157.3 517.65,1163 561.65,1163 517.65,1225 561.65,1225 2632.95,1243.9 2677.85,1273 2636.65,1283.4 2422.89,1389.89 2474.07,1389.9 1636.3,1394.3 1671.3,1394.3 2616.55,1400.1 2682.75,1400 1606.75,1479.5 1638.75,1479.5 1669.75,1479.5 1700.75,1479.5 2379.85,1535 2326.55,1538.9 2435.5,1539.3 2463.5,1539.3 2407.5,1539.5 2496.35,1539.5 2354.35,1546.8 2422.9,1565.2 2373.95,1567 2397.8,1582.2 2451.5,1585.4 2422.9,1595.2 2369.7,1614.8 2435.35,1627.3 2397.8,1642.9 2453.2,1649.3 48.45,1710.4 1891.65,1738 1931.75,1739 2129.15,1758.6 2016.55,1763 47.95,1771.6 2122.35,1786 2647.75,1813.7 2673.75,1838 1715.95,1843.05 1790.45,1843.05 51.25,1868.1 1715.95,1872.05 1755.95,1872.05 1790.45,1872.05 1715.95,1901.55 1755.95,1901.55 1790.45,1901.55 1720.75,1929.5 1786.75,1932 49.05,1948.4 49.85,2030.8 1412.95,2058 1473.75,2058 3027.75,2087.5 3077.75,2087.5 3127.75,2087.5 3177.75,2087.5 3227.75,2087.5 1927.75,2091.8 1960.75,2091.8 1992.75,2091.8 2023.75,2091.8 3002.75,2112.5 3052.75,2112.5 3102.75,2112.5 3152.75,2112.5 3202.75,2112.5 3252.75,2112.5 1945.75,2135.8 1976.95,2135.85 2007.75,2136.8 2977.75,2137.5 3027.75,2137.5 3077.75,2137.5 3127.75,2137.5 3177.75,2137.5 3227.75,2137.5 2852.75,2162.5 2902.75,2162.5 2952.75,2162.5 3002.75,2162.5 3052.75,2162.5 3102.75,2162.5 3152.75,2162.5 3202.75,2162.5 3252.75,2162.5 2827.75,2187.5 2877.75,2187.5 2927.75,2187.5 2977.75,2187.5 3027.75,2187.5 3077.75,2187.5 3127.75,2187.5 3177.75,2187.5 3227.75,2187.5 2852.75,2212.5 2902.75,2212.5 2952.75,2212.5 3002.75,2212.5 3052.75,2212.5 3102.75,2212.5 3152.75,2212.5 3202.75,2212.5 3252.75,2212.5 2827.75,2237.5 2877.75,2237.5 2927.75,2237.5 2977.75,2237.5 3027.75,2237.5 3077.75,2237.5 3127.75,2237.5 3177.75,2237.5 3227.75,2237.5 2852.75,2262.5 2902.75,2262.5 2952.75,2262.5 3002.75,2262.5 3052.75,2262.5 3102.75,2262.5 3152.75,2262.5 3202.75,2262.5 3252.75,2262.5 2827.75,2287.5 2877.75,2287.5 2927.75,2287.5 2977.75,2287.5 3027.75,2287.5 3077.75,2287.5 2852.75,2312.5 2902.75,2312.5 2952.75,2312.5 3002.75,2312.5 2477.75,2337.5 2827.75,2337.5 2877.75,2337.5 2927.75,2337.5 2977.75,2337.5 2852.75,2362.5 2902.75,2362.5 2952.75,2362.5 3002.75,2362.5 2477.75,2387.5 2827.75,2387.5 2877.75,2387.5 2927.75,2387.5 2977.75,2387.5 2852.75,2412.5 2902.75,2412.5 2952.75,2412.5 3002.75,2412.5 2477.75,2437.5 2827.75,2437.5 2877.75,2437.5 2927.75,2437.5 2977.75,2437.5 2852.75,2462.5 2902.75,2462.5 2952.75,2462.5 3002.75,2462.5 2477.75,2487.5 2527.75,2487.5 2577.75,2487.5 2627.75,2487.5 2677.75,2487.5 2727.75,2487.5 2777.75,2487.5 2827.75,2487.5 2877.75,2487.5 2927.75,2487.5 2977.75,2487.5 506.75,2503.5 2552.75,2512.5 2602.75,2512.5 2652.75,2512.5 2702.75,2512.5 2752.75,2512.5 2802.75,2512.5 2852.75,2512.5 2902.75,2512.5 2952.75,2512.5 3002.75,2512.5
  other v2: 2380.42,614.44 2359.75,635.11 2380.42,635.11 2401.09,635.11 2339.08,655.78 2359.75,655.78 2380.42,655.78 2401.09,655.78 2421.76,655.78 2318.41,676.45 2339.08,676.45 2359.75,676.45 2380.42,676.45 2401.09,676.45 2421.76,676.45 2442.43,676.45 2380.42,697.12 2401.09,697.12 2421.76,697.12 2442.43,697.12 2463.1,697.12 2401.09,717.79 2421.76,717.79 2442.43,717.79 2463.1,717.79 2483.77,717.79 2401.09,738.46 2421.76,738.46 2442.43,738.46 2463.1,738.46 2483.77,738.46 2504.44,738.46 2442.43,759.13 2463.1,759.13 2483.77,759.13 2504.44,759.13 2525.11,759.13 2463.1,779.8 2483.77,779.8 2504.44,779.8 2525.11,779.8 2545.78,779.8 2463.1,800.47 2483.77,800.47 2504.44,800.47 2525.11,800.47 2545.78,800.47 2566.45,800.47 2504.44,821.14 2525.11,821.14 2545.78,821.14 2566.45,821.14 2587.12,821.14 2711.14,821.14 2735.46,823.96 2756.13,823.96 2511.05,841 2545.78,841.81 2566.45,841.81 2587.12,841.81 2607.79,841.81 2628.46,841.81 2649.13,841.81 2669.8,841.81 2690.47,841.81 2711.14,841.81 2735.46,844.63 2756.13,844.63 2488.95,847.3 2527.15,854.7 2508.25,863.6 2600.95,865 2622.85,864.6 2645.05,865 2688.85,864.8 2710.45,864.8 2735.46,865.23 2756.13,865.23 2578.85,866 2667.95,865.6 2556.25,869 2489.15,872.6 2534.15,875 2512.95,883.9 2601.44,885.9 2622.11,885.9 2642.78,885.9 2663.45,885.9 2684.12,885.9 2704.79,885.9 2725.46,885.9 2746.13,885.9 2580.79,886.8 2467.15,890.3 2560.35,889.9 2492.85,894.2 2540.56,895.9 2521.58,904.1 2477.15,908.3 2503.65,914.39 2594.33,920.8 2615,920.8 2635.67,920.8 2656.34,920.8 2677.01,920.8 2697.68,920.8 2718.35,920.8 2739.02,920.8 2759.69,920.8 2462.65,923.2 2573.75,922.8 2387.85,925.9 2408.55,925.9 2487.46,927.3 2429.25,928.2 2553.82,928.3 2534.84,936.5 2367.85,937.4 2448.85,939 2625.45,939 2604.65,939.8 2669.55,940.4 2646.55,941 2691.05,941 2711.85,941 2737.85,940.7 2759.15,941.1 2472.74,941.82 2582.15,942.2 2387.85,946.6 2408.55,946.6 2517.53,947.8 2562.05,948.1 2430.05,953.2 2460.25,958.3 2543.65,958 2727.24,957.83 2747.91,957.83 2502.3,961.8 2691.05,961.67 2645.85,962.6 2587.12,965.83 2367.05,967 2387.85,967.3 2408.55,967.3 2710.15,968.5 2526.15,969.5 2666.15,970.9 2428.05,974.1 2449.45,975.89 2489.25,977.83 2727.24,978.5 2747.91,978.5 2691.05,982.34 2544.65,986.1 2566.45,986.5 2387.85,988 2408.55,988 2586.95,988.9 2518.75,991.3 2642.05,991.3 2709.25,990.6 2666.15,991.6 2441.45,994.95 2367.25,996.3 2478.65,995.58 2610.95,998.2 2727.24,999.17 2747.91,999.17 2691.05,1003.01 2498.95,1004.2 2569.65,1007.3 2549.02,1007.8 2387.85,1008.7 2408.55,1008.7 2590.13,1010.1 2629.35,1010.6 2666.15,1012.3 2708.85,1012.3 2528.98,1012.9 2435.4,1014.72 2471.15,1014.85 2608.92,1018.7 2727.24,1019.84 2747.91,1019.84 2511,1022.95 2646.95,1024.5 2691.05,1023.68 2367.15,1029.4 2387.85,1029.4 2408.55,1029.4 2624.95,1031.77 2666.15,1033 2431.95,1035.11 2467.05,1035.11 2496.55,1037.91 2704.05,1038.8 2727.24,1040.51 2747.91,1040.51 2562.21,1042 2582.76,1044.3 2541.75,1044.95 2636.55,1048.87 2367.15,1050.1 2387.85,1050.1 2408.55,1050.1 2666.15,1053.7 2431.25,1055.74 2465.63,1055.74 2486.95,1056.22 2599.96,1055.8 2525.37,1057.59 2727.24,1061.18 2747.91,1061.18 2574.75,1064.5 2553.65,1065.3 2643.35,1068.4 2387.85,1070.8 2408.55,1070.8 2609.25,1074.27 2666.15,1074.4 2431.32,1076.41 2465.63,1076.41 2482.5,1076.41 2517.75,1076.5 2539.35,1080.7 2727.24,1081.85 2747.91,1081.85 2644.65,1089 2408.55,1091.5 2610.05,1094.93 2666.15,1095.1 2431.32,1097.08 2465.63,1097.08 2482.5,1097.08 2516.81,1097.08 2538.95,1101.35 2727.24,1102.52 2747.91,1102.52 2644.65,1109.67 2610.05,1115.6 2666.15,1115.8 2431.32,1117.75 2465.63,1117.75 2482.5,1117.75 2516.81,1117.75 2538.95,1122.05 2727.24,1123.19 2747.91,1123.19 2644.65,1130.34 2610.05,1136.27 2666.15,1136.5 2431.32,1138.42 2465.63,1138.42 2482.5,1138.42 2516.81,1138.42 2538.95,1142.7 2727.24,1143.86 2747.91,1143.86 2644.65,1151.01 2610.05,1156.94 2666.15,1157.2 2708.45,1157.6 2431.32,1159.09 2465.63,1159.09 2482.5,1159.09 2516.81,1159.09 2538.95,1163.4 2688.95,1162.9 2727.24,1164.53 2747.91,1164.53 320.08,1167.94 340.75,1167.94 361.42,1167.94 2648.45,1171.33 1736.21,1176.93 2613.05,1177.4 2431.32,1179.76 2465.63,1179.76 2482.5,1179.76 2516.81,1179.76 2561.45,1181.9 2593.05,1182.7 2665.23,1183.4 2538.95,1184.25 2685.9,1185.2 2706.57,1185.2 2727.24,1185.2 2747.91,1185.2 2623.15,1195.45 1736.21,1197.6 2431.32,1200.43 2465.63,1200.43 2482.5,1200.43 2516.81,1200.43 2582.05,1200.7 2560.65,1204.1 2538.95,1204.95 2603.95,1205.5 2638.77,1209 2657.75,1217.2 1736.21,1218.27 2678.42,1219.7 2699.09,1219.7 2719.76,1219.7 2740.43,1219.7 2760.65,1219.7 2431.32,1221.1 2465.63,1221.1 2482.5,1221.1 2516.81,1221.1 2538.95,1225.65 2559.65,1225.65 2580.35,1225.65 2602.35,1226.1 2719.76,1240.37 2740.43,1240.37 2760.65,1240.37 2431.32,1241.77 2465.63,1241.77 2482.5,1241.77 2516.81,1241.77 2668.35,1242.1 2689.05,1242.1 2539.05,1246.4 2719.76,1261.04 2740.43,1261.04 2760.65,1261.04 2431.32,1262.44 2465.63,1262.44 2482.5,1262.44 2516.81,1262.44 2538.95,1267 2719.76,1281.71 2740.43,1281.71 2760.65,1281.71 2431.32,1283.11 2465.63,1283.11 2482.5,1283.11 2516.81,1283.11 2538.95,1287.85 2719.76,1302.38 2740.43,1302.38 2760.65,1302.38 2431.32,1303.78 2465.63,1303.78 2482.5,1303.78 2516.81,1303.78 2664.55,1304.7 2687.95,1304.9 2719.76,1323.05 2740.43,1323.05 2760.65,1323.05 2431.32,1324.45 2465.63,1324.45 2482.5,1324.45 2516.81,1324.45 2664.75,1329 2686.55,1330.2 2719.76,1343.72 2740.43,1343.72 2760.65,1343.72 2431.32,1345.12 2465.63,1345.12 2482.5,1345.12 2516.81,1345.12 2665.35,1351.2 2686.15,1351.4 2719.76,1364.39 2740.43,1364.39 2760.65,1364.39 2431.32,1365.79 2465.63,1365.79 2482.5,1365.79 2516.81,1365.79 2663.65,1372.7 2691.65,1375 2719.76,1385.06 2740.43,1385.06 2760.65,1385.06 2516.81,1386.46 2644.85,1394.8 2719.76,1405.73 2740.43,1405.73 2760.65,1405.73 2431.32,1407.13 2465.63,1407.13 2482.5,1407.13 2516.81,1407.13 2658.45,1422.4 2632.95,1426.5 2719.76,1426.4 2740.43,1426.4 2760.65,1426.4 2431.32,1427.8 2465.63,1427.8 2482.5,1427.8 2516.81,1427.8 2609.05,1428.2 2681.85,1429.6 2661.35,1446.4 2719.76,1447.07 2740.43,1447.07 2760.65,1447.07 2431.32,1448.47 2465.63,1448.47 2482.5,1448.47 2516.81,1448.47 2615.05,1447.6 2639.05,1448.8 2685.45,1454.4 2597.05,1457.8 2218.17,1461.27 2576.43,1461.27 2704.05,1463.4 2431.32,1469.14 2465.63,1469.14 2482.5,1469.14 2516.81,1469.14 2422.89,1486.86 2474.07,1486.86 2525.25,1486.86 2576.43,1486.86 2702.75,1492.5 2726.81,1495.24 2747.48,1495.24 2682.85,1499.1 2433.12,1504.57 2463.83,1504.57 2484.3,1504.57 2515.01,1504.57 2448.48,1512.45 2499.66,1512.45 2576.43,1512.45 2726.81,1515.91 2747.48,1515.91 2694.85,1517.2 2673.05,1517.9 2747.75,1536.5 2706.14,1536.58 2726.81,1536.58 2685.51,1537.98 2632.05,1541.8 2665.67,1543.78 2613.55,1550.7 2647.8,1554.2 2550.84,1563.63 2629.6,1564.18 2609.81,1570.18 2706.18,1571.08 2726.85,1571.08 2747.52,1571.08 2568.55,1572.07 2589.22,1572.07 2685.62,1573.28 2533.12,1573.86 2667.15,1582.58 2525.25,1589.22 2735.15,1589.4 2756.55,1590 2649.3,1593.03 2688.06,1599.68 2630,1600.58 2708.73,1600.58 2667.51,1601.88 2533.12,1604.57 2609.81,1605.08 2568.55,1606.37 2589.22,1606.37 2727.75,1608.5 2648.7,1610.47 2748.08,1611.29 2550.84,1614.81 2630.35,1620.08 2568.55,1623.25 2589.22,1623.25 2609.89,1623.25 2533.12,1625.04 2687.65,1634.48 2708.05,1637.78 2525.25,1640.4 2667.65,1639.68 2727.15,1645.68 2747.82,1645.68 2649.6,1649.77 2680.35,1655.4 2533.12,1655.75 2630.48,1655.68 2700.45,1656.1 2568.55,1657.55 2589.22,1657.55 2609.89,1657.55 2662.25,1665.1 2550.84,1665.99 2719.45,1666.5 2739.75,1666.5 2759.55,1665.6 2568.55,1674.43 2589.22,1674.43 2609.89,1674.43 2700.45,1675.2 2533.12,1676.23 2630.48,1676.3 2680.15,1677 2649.6,1682.21 2727.15,1686.3 2747.75,1685.5 2525.25,1691.58 2667.65,1692.3 2708.05,1694.2 2687.65,1697.5 2533.12,1706.93 2568.55,1708.73 2589.22,1708.73 2609.89,1708.73 2630.35,1711.9 2550.84,1717.17 2748.08,1720.69 2648.7,1721.51 2727.75,1723.5 2568.55,1725.61 2589.22,1725.61 2533.12,1727.41 2609.81,1726.9 2667.51,1730.1 2630,1731.4 2708.73,1731.4 2688.06,1732.3 2649.3,1738.95 2733.25,1741.8 2755.25,1742.4 2525.25,1742.76 2667.15,1749.4 2533.12,1758.11 2685.62,1758.7 2568.55,1759.91 2589.22,1759.91 2706.18,1760.9 2726.85,1760.9 2747.52,1760.9 2609.81,1761.8 2550.87,1768.35 2629.6,1767.8 2647.8,1777.78 2617.45,1784.6 2665.67,1788.2 2685.51,1794 2706.14,1795.4 2726.81,1795.4 2747.48,1795.4 2717.45,1813.03 2759.55,1812.6 2677.75,1814.1 2739.45,1813.5 2697.45,1816 2738.88,1833.27 2759.55,1833.27 2717.45,1833.7 2697.65,1838.5 2716.15,1858.6 2695.05,1868.8 2737.75,1869.1 2759.45,1869.5 2710.45,1883.3 2239.22,2330.24 2259.89,2330.24 2280.56,2330.24 2301.23,2330.24 2321.9,2330.24 2342.57,2330.24 2363.24,2330.24 2383.91,2330.24 2404.58,2330.24 2218.55,2331.7 2425.25,2331.7 2197.82,2347.4 2442.55,2347.4 2218.55,2363.1 2425.25,2363.1 2239.22,2364.56 2259.89,2364.56 2280.56,2364.56 2301.23,2364.56 2321.9,2364.56 2342.57,2364.56 2363.24,2364.56 2383.91,2364.56 2404.58,2364.56 1766.05,2418.34 1786.72,2418.34 1807.39,2418.34 1828.06,2418.34 1848.73,2418.34 1869.4,2418.34 1890.07,2418.34 1910.74,2418.34 1931.41,2418.34 1952.08,2418.34 1972.75,2418.34 1993.42,2418.34 2014.09,2418.34 2034.76,2418.34 2055.43,2418.34 2076.1,2418.34 2096.77,2418.34 2117.44,2418.34 2138.11,2418.34 2158.78,2418.34 2179.45,2418.34 2200.12,2418.34 2220.79,2418.34 2241.46,2418.34 2262.13,2418.34 2282.8,2418.34 2303.47,2418.34 2324.14,2418.34 2344.81,2418.34 2365.48,2418.34 2386.15,2418.34 2406.82,2418.34 1745.38,2419.8 2427.44,2419.8 1722.45,2435.5 2443.35,2435.5 1745.38,2451.2 2427.44,2451.2 1766.05,2452.66 1786.72,2452.66 1807.39,2452.66 1828.06,2452.66 1848.73,2452.66 1869.4,2452.66 1890.07,2452.66 1910.74,2452.66 1931.41,2452.66 1952.08,2452.66 1972.75,2452.66 1993.42,2452.66 2014.09,2452.66 2034.76,2452.66 2055.43,2452.66 2076.1,2452.66 2096.77,2452.66 2117.44,2452.66 2138.11,2452.66 2158.78,2452.66 2179.45,2452.66 2200.12,2452.66 2220.79,2452.66 2241.46,2452.66 2262.13,2452.66 2282.8,2452.66 2303.47,2452.66 2324.14,2452.66 2344.81,2452.66 2365.48,2452.66 2386.15,2452.66 2406.82,2452.66
  other v3: 2101.25,1052.79 2140.61,1052.79 2101.25,1092.16 2140.61,1092.16 1619.5,1243 1653.75,1243 1688,1243 1757.37,1843.51 1757.37,1930.13
LDO_01_EN: R83.1 R84.2 U4.5 | length 104.6
  TOP w13: R84.2@2019,1013.72 2019.39,1014.11 2019.68,1014.4 2019.79,1014.4 U4.5@2082.54,1014.4
  TOP w20: R84.2@2019,1013.72 R83.1@2019,1054.52
LDO_02_EN: R46.2 R47.1 U5.6 U5.20 | length 642
  TOP w4: R47.1@1545.15,1869.5 1587.75,1869.5 1588.35,1868.9 R46.2@1588.35,1868.11 1588.35,1818.9 1623.75,1783.5 1647.75,1783.5 v1(1649.95,1785.7)
  L4-GND/SIG w5: v1(1649.95,1785.7) 1615.65,1820 1615.65,1966.2 1647.75,1998.3 1647.75,2014.6 v1(1674.25,2041.1)
  BOTTOM w4: v1(1649.95,1785.7) 1706.74,1785.7 1718,1796.96 U5.20@1718,1808.08 ; v1(1674.25,2041.1) 1674.25,2020.9 1718,1977.15 U5.6@1718,1965.56
MCU_3V3: J4.3 J6.1 R130.1 | length 3047.1
  TOP w35: v1(815.75,545) 816.25,545.5 1331.25,545.5 v1(1375.75,590) ; v1(1534.56,1800.19) 1534.56,1816.09 1494.75,1855.9 1494.75,2026.3 1556.35,2087.9 1601.75,2087.9 1636.75,2122.9 v1(1636.75,2152.4)
  L4-GND/SIG w35: v1(1375.75,590) 1375.75,590.07 1382.45,596.77 1382.45,1214.3 1338.75,1258 1338.75,1428.4 1373.45,1463.1 1373.45,1553.2 1534.56,1714.31 v1(1534.56,1800.19)
  BOTTOM w35: R130.1@1534.56,1761.21 v1(1534.56,1800.19) ; v1(1636.75,2152.4) 1636.75,2203.8 1691.15,2258.2 1742.45,2258.2 1876.23,2391.98 J4.3@1930.25,2391.98
  BOTTOM w40: J6.1@630.25,460.78 630.25,494.79 680.46,545 v1(815.75,545)
MCU_5V: J6.2 J7.3 R115.1 | length 113.2
  BOTTOM w40: v1(593.75,729.5) 593.75,727.5 630.25,691 J6.2@630.25,683.22 657.47,656 v1(670.75,656)
  other v1: 1944.75,538 1897.75,540 1887.75,575 1891.75,612 544.75,728.5 666.75,731.5
MCU_SOP0: R36.1 R93.2 | length 1743.3
  TOP w4: R93.2@1108.57,729.45 1110.89,729.45 1132.95,751.51 1132.95,820.7 v1(1136.95,824.7) ; v1(1490.75,2118) 1498.98,2126.23 R36.1@1530,2126.23
  BOTTOM w4: v1(1136.95,824.7) 1312.95,1000.7 1312.95,1164.7 1262.15,1215.5 1262.15,1257.8 1285.63,1281.28 1285.63,1290.06 1309.71,1314.14 1309.71,1325.96 1309.75,1326 1309.75,1550.1 1305.25,1554.6 1305.25,1575.4 1315.75,1585.9 1315.75,1842.3 1251.75,1906.3 1251.75,1970.5 1375.85,2094.6 1467.35,2094.6 v1(1490.75,2118)
MCU_SOP1: R35.1 R112.2 | length 2050.4
  TOP w4: R112.2@752.07,591.15 766.79,591.15 795.35,619.71 795.35,691.1 858.95,754.7 998.35,754.7 v1(1024.35,780.7) ; v1(1393.75,2126) 1394.75,2126 1394.75,2126.23 R35.1@1429.5,2126.23
  BOTTOM w4: v1(1024.35,780.7) 1113.45,869.8 1155.05,869.8 1303.95,1018.7 1303.95,1152.92 1253.15,1203.72 1253.15,1261.53 1276.63,1285.01 1276.63,1293.79 1300.71,1317.87 1300.71,1329.82 1300.75,1329.86 1300.75,1541.5 1295.85,1546.4 1295.85,1579 1306.75,1589.9 1306.75,1833.7 1242.75,1897.7 1242.75,1974.5 1393.75,2125.5 v1(1393.75,2126)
